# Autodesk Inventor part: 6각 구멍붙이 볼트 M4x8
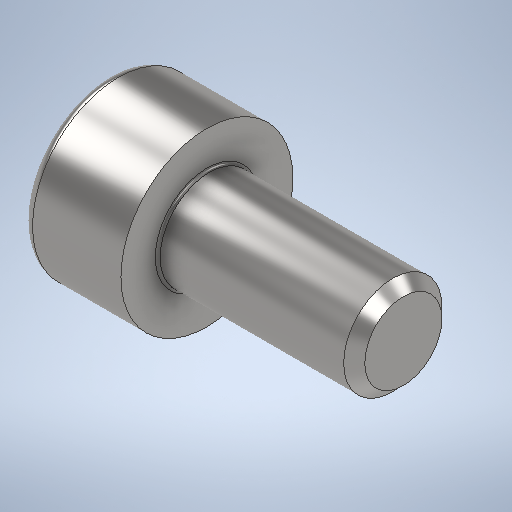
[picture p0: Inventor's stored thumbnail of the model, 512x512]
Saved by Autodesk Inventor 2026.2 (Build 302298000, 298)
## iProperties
Created: 2026-06
Part Number: 6각 구멍붙이 볼트 M4x8
Material: 강철, 연강
Description: 6각머리 태핑 나사
Document SubType Name: Modeling
Designer: sec7
Density: 7.85 g/cm^3
Appearance: 기본값
Author: jhkim
Sending System: Autodesk Inventor 2027
Preprocessor: ST-DEVELOPER v20.1
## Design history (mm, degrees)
feature "Solid1"
node "솔리드1"
